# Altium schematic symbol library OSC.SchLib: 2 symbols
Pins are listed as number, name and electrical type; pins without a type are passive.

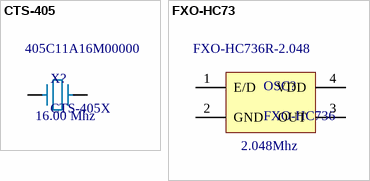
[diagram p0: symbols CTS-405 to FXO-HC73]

## CTS-405
designator X?, comment CTS-405X  value 16.00 Mhz  Manufacturer Part Number: 405C11A16M00000
CTS 405 Series Crystal Oscillator; Manufacturer: CTS-Frequency Controls; Description: CRYSTAL 16MHZ 10PF SMD; Frequency: 16MHz; Frequency Stability: ±10ppm; Load Capacitance: 10pF; ESR (Equivalent Series Resistance): 60 Ohm; Operating Mode: Fundamental
footprint 405XO (CTS 405 Series Crystal Oscillator)
pins: 1, 3

## FXO-HC73
designator OSC?, comment FXO-HC736  value 2.048Mhz  Manufacturer Part Number: FXO-HC736R-2.048
FXO-HC73 Series Oscillator; Manufacturer: Fox Electronics; Description: OSC XO 2.048MHZ HCMOS SMD; Function: Tri-State (Output Enable); Output: HCMOS; Voltage - Supply: 3.3V; Frequency Stability: ±25ppm; Current - Supply (Max): 32mA
footprint HC73 (FXO HC73 Series Oscillator)
pins: 1 E/D, 2 GND, 3 OUT, 4 VDD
